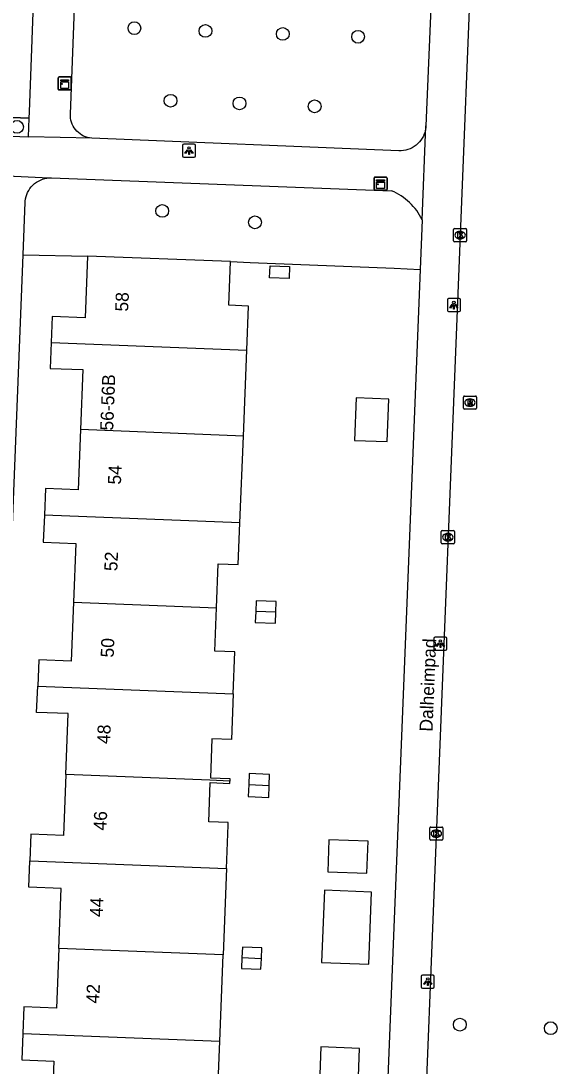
# Model space of a CAD drawing. Extents: x 160787 to 161428, y 386828 to 387483.
# Drawn here: x 161096.6 to 161137.7, y 387090.3 to 387170.3 of the extents above; entities that cross this region are included whole.
import ezdxf

# ---------------------------------------------------------------- set-up
doc = ezdxf.new("R2010")
doc.units = 0
for name, color, linetype in [('IMGEO_Boom', 7, 'Continuous'), ('IMGEO_Groenvoorziening', 7, 'Continuous'), ('IMGEO_Haag', 7, 'Continuous'), ('IMGEO_Hek', 7, 'Continuous'), ('IMGEO_Kast', 7, 'Continuous'), ('IMGEO_Kolk', 7, 'Continuous'), ('IMGEO_Lichtpunt', 7, 'Continuous'), ('IMGEO_Openbare_ruimte_label', 7, 'Continuous'), ('IMGEO_Pand', 7, 'Continuous'), ('IMGEO_Pand_nummerreeks', 7, 'Continuous'), ('IMGEO_Rioolput', 7, 'Continuous'), ('IMGEO_Voetpad_open', 7, 'Continuous')]:
    doc.layers.add(name, color=color, linetype=linetype)

msp = doc.modelspace()

# ---------------------------------------------------------------- linework, layer by layer
at = {"layer": 'IMGEO_Boom'}
for centre in [(161105.276, 387169.754), (161110.722, 387169.544), (161116.648, 387169.315), (161122.413, 387169.092), (161108.043, 387164.193), (161113.329, 387163.989), (161119.085, 387163.766), (161096.289, 387162.196), (161107.406, 387155.761), (161114.516, 387154.886), (161130.212, 387093.447), (161137.176, 387093.174)]:
    msp.add_circle(centre, 0.489, dxfattribs=at)
at = {"layer": 'IMGEO_Groenvoorziening'}
for points in [[(161095.222, 387162.927), (161097.214, 387162.854)], [(161096.743, 387152.402), (161101.691, 387152.304)], [(161112.644, 387151.876), (161114.144, 387151.817), (161125.178, 387151.362), (161127.175, 387151.273)]]:
    msp.add_lwpolyline(points, dxfattribs=at)
at = {"layer": 'IMGEO_Haag'}
msp.add_lwpolyline([(161097.214, 387162.854), (161095.222, 387162.927)], dxfattribs=at)
at = {"layer": 'IMGEO_Hek'}
msp.add_lwpolyline([(161097.214, 387162.854), (161087.423, 387163.212), (161083.345, 387163.361), (161081.407, 387163.432), (161075.331, 387163.654), (161075.116, 387163.662), (161074.598, 387163.681), (161071.304, 387163.802), (161070.928, 387163.815), (161063.158, 387164.099), (161059.142, 387164.246), (161052.353, 387164.535), (161051.029, 387164.592), (161046.982, 387164.764), (161046.647, 387164.778), (161038.81, 387165.111), (161034.783, 387165.283), (161026.6, 387165.631), (161022.975, 387165.785), (161022.636, 387165.799), (161014.462, 387166.146), (161011.004, 387166.293), (161000.917, 387166.722)], dxfattribs=at)
at = {"layer": 'IMGEO_Kast'}
for p, q in [((161099.438, 387165.094), (161099.438, 387165.935)), ((161099.438, 387165.935), (161099.438, 387165.094)), ((161099.513, 387166.019), (161100.354, 387166.019)), ((161100.354, 387166.019), (161099.513, 387166.019)), ((161100.438, 387165.944), (161100.438, 387165.103)), ((161100.438, 387165.103), (161100.438, 387165.944)), ((161100.363, 387165.019), (161099.522, 387165.019)), ((161099.522, 387165.019), (161100.363, 387165.019)), ((161123.637, 387157.414), (161123.637, 387158.255)), ((161123.637, 387158.255), (161123.637, 387157.414)), ((161123.712, 387158.339), (161124.553, 387158.339)), ((161124.553, 387158.339), (161123.712, 387158.339)), ((161124.637, 387158.264), (161124.637, 387157.423)), ((161124.637, 387157.423), (161124.637, 387158.264)), ((161124.562, 387157.339), (161123.721, 387157.339)), ((161123.721, 387157.339), (161124.562, 387157.339))]:
    msp.add_line(p, q, dxfattribs=at)
for points in [[(161099.633, 387165.809), (161100.233, 387165.809), (161100.233, 387165.724), (161099.633, 387165.724), (161099.633, 387165.809)], [(161099.633, 387165.634), (161100.233, 387165.634), (161100.233, 387165.145), (161099.633, 387165.145), (161099.633, 387165.634)], [(161123.832, 387158.129), (161124.432, 387158.129), (161124.432, 387158.044), (161123.832, 387158.044), (161123.832, 387158.129)], [(161123.832, 387157.954), (161124.432, 387157.954), (161124.432, 387157.465), (161123.832, 387157.465), (161123.832, 387157.954)]]:
    msp.add_lwpolyline(points, dxfattribs=at)
for centre in [(161099.717, 387165.483), (161123.916, 387157.803)]:
    msp.add_circle(centre, 0.0377, dxfattribs=at)
for centre, start, end in [((161099.516, 387165.941), 92.4484, 184.28452), ((161099.516, 387165.941), 92.4484, 184.28452), ((161100.36, 387165.941), 2.4484, 94.28452), ((161100.36, 387165.941), 2.4484, 94.28452), ((161099.516, 387165.097), 182.4484, 274.28452), ((161099.516, 387165.097), 182.4484, 274.28452), ((161100.36, 387165.097), 272.4484, 4.28452), ((161100.36, 387165.097), 272.4484, 4.28452), ((161123.715, 387158.261), 92.4484, 184.28452), ((161123.715, 387158.261), 92.4484, 184.28452), ((161124.559, 387158.261), 2.4484, 94.28452), ((161124.559, 387158.261), 2.4484, 94.28452), ((161123.715, 387157.417), 182.4484, 274.28452), ((161123.715, 387157.417), 182.4484, 274.28452), ((161124.559, 387157.417), 272.4484, 4.28452), ((161124.559, 387157.417), 272.4484, 4.28452)]:
    msp.add_arc(centre, 0.0779, start, end, dxfattribs=at)
at = {"layer": 'IMGEO_Kolk'}
for p, q in [((161129.733, 387153.477), (161129.733, 387154.329)), ((161129.808, 387154.403), (161130.66, 387154.403)), ((161130.221, 387154.183), (161130.246, 387154.183)), ((161130.734, 387154.329), (161130.734, 387153.477)), ((161130.66, 387153.403), (161129.808, 387153.403)), ((161130.244, 387153.623), (161130.219, 387153.623)), ((161128.867, 387131.275), (161129.719, 387131.275)), ((161128.792, 387130.349), (161128.792, 387131.201)), ((161129.303, 387130.495), (161129.278, 387130.495)), ((161129.28, 387131.055), (161129.305, 387131.055)), ((161129.793, 387131.201), (161129.793, 387130.349)), ((161129.719, 387130.275), (161128.867, 387130.275)), ((161127.906, 387107.655), (161127.906, 387108.507)), ((161127.981, 387108.581), (161128.833, 387108.581)), ((161128.394, 387108.361), (161128.419, 387108.361)), ((161128.907, 387108.507), (161128.907, 387107.655)), ((161128.833, 387107.581), (161127.981, 387107.581)), ((161128.417, 387107.801), (161128.392, 387107.801))]:
    msp.add_line(p, q, dxfattribs=at)
for points in [[(161129.733, 387153.477), (161129.733, 387154.329)], [(161129.808, 387154.403), (161130.66, 387154.403)], [(161130.054, 387154.103), (161130.177, 387154.103), (161130.177, 387153.952), (161130.307, 387154.103), (161130.471, 387154.103), (161130.325, 387153.952), (161130.478, 387153.703), (161130.326, 387153.703), (161130.241, 387153.867), (161130.177, 387153.8), (161130.177, 387153.703), (161130.054, 387153.703), (161130.054, 387154.103)], [(161130.734, 387154.329), (161130.734, 387153.477)], [(161130.66, 387153.403), (161129.808, 387153.403)], [(161128.867, 387131.275), (161129.719, 387131.275)], [(161128.792, 387130.349), (161128.792, 387131.201)], [(161129.113, 387130.975), (161129.236, 387130.975), (161129.236, 387130.824), (161129.366, 387130.975), (161129.53, 387130.975), (161129.384, 387130.824), (161129.537, 387130.575), (161129.385, 387130.575), (161129.3, 387130.739), (161129.236, 387130.672), (161129.236, 387130.575), (161129.113, 387130.575), (161129.113, 387130.975)], [(161129.793, 387131.201), (161129.793, 387130.349)], [(161129.719, 387130.275), (161128.867, 387130.275)], [(161127.906, 387107.655), (161127.906, 387108.507)], [(161127.981, 387108.581), (161128.833, 387108.581)], [(161128.227, 387108.281), (161128.35, 387108.281), (161128.35, 387108.13), (161128.48, 387108.281), (161128.644, 387108.281), (161128.498, 387108.13), (161128.651, 387107.881), (161128.499, 387107.881), (161128.414, 387108.045), (161128.35, 387107.978), (161128.35, 387107.881), (161128.227, 387107.881), (161128.227, 387108.281)], [(161128.907, 387108.507), (161128.907, 387107.655)], [(161128.833, 387107.581), (161127.981, 387107.581)]]:
    msp.add_lwpolyline(points, dxfattribs=at)
for centre, start, end in [((161129.81, 387154.327), 91.55205, 178.44795), ((161129.81, 387154.327), 91.55205, 178.44795), ((161130.658, 387154.327), 1.55205, 88.44795), ((161130.658, 387154.327), 1.55205, 88.44795), ((161129.81, 387153.479), 181.55205, 268.44795), ((161129.81, 387153.479), 181.55205, 268.44795), ((161130.658, 387153.479), 271.55205, 358.44795), ((161130.658, 387153.479), 271.55205, 358.44795), ((161128.869, 387131.199), 91.55205, 178.44795), ((161128.869, 387131.199), 91.55205, 178.44795), ((161129.717, 387131.199), 1.55205, 88.44795), ((161129.717, 387131.199), 1.55205, 88.44795), ((161128.869, 387130.351), 181.55205, 268.44795), ((161128.869, 387130.351), 181.55205, 268.44795), ((161129.717, 387130.351), 271.55205, 358.44795), ((161129.717, 387130.351), 271.55205, 358.44795), ((161127.983, 387108.505), 91.55205, 178.44795), ((161127.983, 387108.505), 91.55205, 178.44795), ((161128.831, 387108.505), 1.55205, 88.44795), ((161128.831, 387108.505), 1.55205, 88.44795), ((161127.983, 387107.657), 181.55205, 268.44795), ((161127.983, 387107.657), 181.55205, 268.44795), ((161128.831, 387107.657), 271.55205, 358.44795), ((161128.831, 387107.657), 271.55205, 358.44795)]:
    msp.add_arc(centre, 0.0765, start, end, dxfattribs=at)
for centre, major_axis, ratio, start_param, end_param in [((161130.22, 387153.903), (-0.387, 0.002), 0.722429, 4.712389, 7.853982), ((161130.245, 387153.903), (-0.39, 0.002), 0.717154, 1.570796, 4.712389), ((161129.279, 387130.775), (-0.387, 0.002), 0.722429, 4.712389, 7.853982), ((161129.304, 387130.775), (-0.39, 0.002), 0.717154, 1.570796, 4.712389), ((161128.393, 387108.081), (-0.387, 0.002), 0.722429, 4.712389, 7.853982), ((161128.418, 387108.081), (-0.39, 0.002), 0.717154, 1.570796, 4.712389)]:
    msp.add_ellipse(centre, major_axis=major_axis, ratio=ratio, start_param=start_param, end_param=end_param, dxfattribs=at)
at = {"layer": 'IMGEO_Lichtpunt'}
for p, q in [((161109.864, 387160.874), (161109.056, 387160.874)), ((161109.864, 387160.874), (161109.056, 387160.874)), ((161108.962, 387160.779), (161108.962, 387159.972)), ((161108.962, 387160.779), (161108.962, 387159.972)), ((161109.958, 387159.972), (161109.958, 387160.779)), ((161109.958, 387159.972), (161109.958, 387160.779)), ((161109.056, 387159.878), (161109.864, 387159.878)), ((161109.056, 387159.878), (161109.864, 387159.878)), ((161129.26, 387148.947), (161129.26, 387148.14)), ((161129.26, 387148.947), (161129.26, 387148.14)), ((161130.162, 387149.042), (161129.354, 387149.042)), ((161130.162, 387149.042), (161129.354, 387149.042)), ((161130.256, 387148.14), (161130.256, 387148.947)), ((161130.256, 387148.14), (161130.256, 387148.947)), ((161129.354, 387148.046), (161130.162, 387148.046)), ((161129.354, 387148.046), (161130.162, 387148.046)), ((161128.22, 387123.027), (161128.22, 387122.22)), ((161128.22, 387123.027), (161128.22, 387122.22)), ((161129.122, 387123.122), (161128.314, 387123.122)), ((161129.122, 387123.122), (161128.314, 387123.122)), ((161129.216, 387122.22), (161129.216, 387123.027)), ((161129.216, 387122.22), (161129.216, 387123.027)), ((161128.314, 387122.126), (161129.122, 387122.126)), ((161128.314, 387122.126), (161129.122, 387122.126)), ((161127.256, 387097.145), (161127.256, 387096.338)), ((161127.256, 387097.145), (161127.256, 387096.338)), ((161128.158, 387097.24), (161127.35, 387097.24)), ((161128.158, 387097.24), (161127.35, 387097.24)), ((161128.252, 387096.338), (161128.252, 387097.145)), ((161128.252, 387096.338), (161128.252, 387097.145)), ((161127.35, 387096.244), (161128.158, 387096.244)), ((161127.35, 387096.244), (161128.158, 387096.244))]:
    msp.add_line(p, q, dxfattribs=at)
for points in [[(161109.336, 387160.443), (161109.375, 387160.415), (161109.187, 387160.153), (161109.149, 387160.18), (161109.336, 387160.443)], [(161109.438, 387160.395), (161109.485, 387160.395), (161109.485, 387160.073), (161109.438, 387160.073), (161109.438, 387160.395)], [(161109.548, 387160.415), (161109.586, 387160.442), (161109.773, 387160.18), (161109.734, 387160.152), (161109.548, 387160.415)], [(161129.634, 387148.611), (161129.673, 387148.583), (161129.485, 387148.321), (161129.447, 387148.348), (161129.634, 387148.611)], [(161129.736, 387148.563), (161129.783, 387148.563), (161129.783, 387148.241), (161129.736, 387148.241), (161129.736, 387148.563)], [(161129.846, 387148.583), (161129.884, 387148.61), (161130.071, 387148.348), (161130.032, 387148.32), (161129.846, 387148.583)], [(161128.594, 387122.691), (161128.633, 387122.663), (161128.445, 387122.401), (161128.407, 387122.428), (161128.594, 387122.691)], [(161128.696, 387122.643), (161128.743, 387122.643), (161128.743, 387122.321), (161128.696, 387122.321), (161128.696, 387122.643)], [(161128.806, 387122.663), (161128.844, 387122.69), (161129.031, 387122.428), (161128.992, 387122.4), (161128.806, 387122.663)], [(161127.63, 387096.809), (161127.669, 387096.781), (161127.481, 387096.519), (161127.443, 387096.546), (161127.63, 387096.809)], [(161127.732, 387096.761), (161127.779, 387096.761), (161127.779, 387096.439), (161127.732, 387096.439), (161127.732, 387096.761)], [(161127.842, 387096.781), (161127.88, 387096.808), (161128.067, 387096.546), (161128.028, 387096.518), (161127.842, 387096.781)]]:
    msp.add_lwpolyline(points, dxfattribs=at)
for centre in [(161109.461, 387160.577), (161129.759, 387148.745), (161128.719, 387122.825), (161127.755, 387096.943)]:
    msp.add_circle(centre, 0.0994, dxfattribs=at)
for centre, start, end in [((161109.056, 387160.779), 90, 180), ((161109.056, 387160.779), 90, 180), ((161109.864, 387160.779), 0, 90), ((161109.864, 387160.779), 0, 90), ((161109.056, 387159.972), 180, 270), ((161109.056, 387159.972), 180, 270), ((161109.864, 387159.972), 270, 0), ((161109.864, 387159.972), 270, 360), ((161129.354, 387148.947), 90, 180), ((161129.354, 387148.947), 90, 180), ((161130.162, 387148.947), 0, 90), ((161130.162, 387148.947), 0, 90), ((161129.354, 387148.14), 180, 270), ((161129.354, 387148.14), 180, 270), ((161130.162, 387148.14), 270, 0), ((161130.162, 387148.14), 270, 360), ((161128.314, 387123.027), 90, 180), ((161128.314, 387123.027), 90, 180), ((161129.122, 387123.027), 0, 90), ((161129.122, 387123.027), 0, 90), ((161128.314, 387122.22), 180, 270), ((161128.314, 387122.22), 180, 270), ((161129.122, 387122.22), 270, 0), ((161129.122, 387122.22), 270, 360), ((161127.35, 387097.145), 90, 180), ((161127.35, 387097.145), 90, 180), ((161128.158, 387097.145), 0, 90), ((161128.158, 387097.145), 0, 90), ((161127.35, 387096.338), 180, 270), ((161127.35, 387096.338), 180, 270), ((161128.158, 387096.338), 270, 0), ((161128.158, 387096.338), 270, 360)]:
    msp.add_arc(centre, 0.0946, start, end, dxfattribs=at)
at = {"layer": 'IMGEO_Pand'}
for points in [[(161101.691, 387152.304), (161101.506, 387147.562), (161098.987, 387147.661), (161098.909, 387145.68)], [(161112.644, 387151.876), (161101.691, 387152.304)], [(161113.881, 387145.095), (161114.013, 387148.471), (161112.513, 387148.53), (161112.644, 387151.876)], [(161115.672, 387151.557), (161117.16, 387151.498), (161117.124, 387150.578), (161115.636, 387150.637), (161115.672, 387151.557)], [(161098.909, 387145.68), (161098.832, 387143.701), (161101.33, 387143.603), (161101.151, 387139.008)], [(161098.909, 387145.68), (161113.881, 387145.095)], [(161113.624, 387138.52), (161113.881, 387145.095)], [(161124.775, 387141.336), (161122.277, 387141.434), (161122.147, 387138.187), (161124.645, 387138.089), (161124.775, 387141.336)], [(161101.151, 387139.008), (161100.971, 387134.408), (161098.457, 387134.506), (161098.376, 387132.45)], [(161113.624, 387138.52), (161101.151, 387139.008)], [(161113.364, 387131.864), (161113.624, 387138.52)], [(161098.376, 387132.45), (161098.296, 387130.396), (161100.781, 387130.299), (161100.605, 387125.795)], [(161113.364, 387131.864), (161098.376, 387132.45)], [(161111.571, 387125.366), (161111.703, 387128.73), (161113.239, 387128.67), (161113.364, 387131.864)], [(161100.605, 387125.795), (161100.429, 387121.288), (161097.943, 387121.386), (161097.864, 387119.372)], [(161100.605, 387125.795), (161111.571, 387125.366)], [(161116.113, 387125.025), (161116.144, 387125.838), (161114.607, 387125.898), (161114.575, 387125.085)], [(161112.853, 387118.786), (161112.978, 387121.99), (161111.442, 387122.05), (161111.571, 387125.366)], [(161114.575, 387125.085), (161114.542, 387124.248), (161116.08, 387124.188), (161116.113, 387125.025)], [(161116.113, 387125.025), (161114.575, 387125.085)], [(161100.026, 387112.595), (161100.208, 387117.265), (161097.786, 387117.36), (161097.864, 387119.372)], [(161097.864, 387119.372), (161112.853, 387118.786)], [(161112.853, 387118.786), (161112.716, 387115.282), (161111.216, 387115.34), (161111.099, 387112.342), (161112.598, 387112.284), (161112.591, 387112.104)], [(161100.026, 387112.595), (161099.843, 387107.923), (161097.349, 387108.021), (161097.27, 387105.995)], [(161112.591, 387112.104), (161111.055, 387112.164), (161100.026, 387112.595)], [(161112.33, 387105.406), (161112.46, 387108.732), (161112.467, 387108.926), (161110.968, 387108.985), (161111.085, 387111.983), (161112.584, 387111.924), (161112.591, 387112.104)], [(161115.605, 387111.767), (161115.638, 387112.61), (161114.069, 387112.672), (161114.036, 387111.828)], [(161114.036, 387111.828), (161114, 387110.913), (161115.569, 387110.851), (161115.605, 387111.767)], [(161114.036, 387111.828), (161115.605, 387111.767)], [(161120.09, 387105.159), (161123.097, 387105.058), (161123.18, 387107.501), (161120.172, 387107.602), (161120.09, 387105.159)], [(161099.476, 387099.29), (161099.656, 387103.875), (161097.191, 387103.971), (161097.27, 387105.995)], [(161097.27, 387105.995), (161112.33, 387105.406)], [(161112.33, 387105.406), (161112.071, 387098.797)], [(161119.618, 387098.218), (161123.227, 387098.077), (161123.443, 387103.596), (161119.834, 387103.737), (161119.618, 387098.218)], [(161099.476, 387099.29), (161099.297, 387094.705), (161096.813, 387094.802), (161096.734, 387092.778)], [(161112.071, 387098.797), (161099.476, 387099.29)], [(161115.006, 387098.517), (161115.038, 387099.326), (161113.546, 387099.385), (161113.514, 387098.576)], [(161111.813, 387092.188), (161112.071, 387098.797)], [(161113.514, 387098.576), (161113.482, 387097.756), (161114.974, 387097.697), (161115.006, 387098.517)], [(161113.514, 387098.576), (161115.006, 387098.517)], [(161096.734, 387092.778), (161096.655, 387090.756), (161099.09, 387090.661), (161098.911, 387086.078)], [(161096.734, 387092.778), (161111.813, 387092.188)], [(161109.909, 387085.648), (161110.043, 387089.094), (161111.69, 387089.03), (161111.813, 387092.188)], [(161119.489, 387089.621), (161122.448, 387089.506), (161122.531, 387091.622), (161119.572, 387091.737), (161119.489, 387089.621)]]:
    msp.add_lwpolyline(points, dxfattribs=at)
at = {"layer": 'IMGEO_Rioolput'}
for p, q in [((161130.484, 387140.657), (161130.484, 387141.509)), ((161130.559, 387141.583), (161131.411, 387141.583)), ((161130.972, 387141.363), (161130.997, 387141.363)), ((161131.485, 387141.509), (161131.485, 387140.657)), ((161131.411, 387140.583), (161130.559, 387140.583)), ((161130.995, 387140.803), (161130.97, 387140.803))]:
    msp.add_line(p, q, dxfattribs=at)
for points in [[(161130.484, 387140.657), (161130.484, 387141.509)], [(161130.559, 387141.583), (161131.411, 387141.583)], [(161131.073, 387141.281), (161130.821, 387141.283), (161130.821, 387140.883)], [(161130.821, 387140.883), (161130.945, 387140.883), (161130.945, 387141.045), (161130.956, 387141.045)], [(161130.999, 387141.202), (161130.945, 387141.202), (161130.945, 387141.121)], [(161130.945, 387141.121), (161130.997, 387141.121)], [(161131.003, 387141.016), (161131.074, 387140.883), (161131.214, 387140.883), (161131.149, 387141.009)], [(161131.485, 387141.509), (161131.485, 387140.657)], [(161131.411, 387140.583), (161130.559, 387140.583)]]:
    msp.add_lwpolyline(points, dxfattribs=at)
for centre, radius, start, end in [((161130.561, 387141.507), 0.0765, 91.55205, 178.44795), ((161130.561, 387141.507), 0.0765, 91.55205, 178.44795), ((161130.955, 387140.992), 0.0533, 26.02933, 88.69889), ((161130.981, 387141.31), 0.19, 274.7715, 282.96867), ((161131.005, 387141.106), 0.0964, 77.00612, 93.18647), ((161131.019, 387141.163), 0.0378, 276.66336, 79.67722), ((161131.072, 387141.171), 0.109, 350.36119, 89.41601), ((161131.07, 387141.171), 0.112, 277.58423, 350.98172), ((161131.054, 387140.956), 0.108, 29.51342, 73.79051), ((161131.409, 387141.507), 0.0765, 1.55205, 88.44795), ((161131.409, 387141.507), 0.0765, 1.55205, 88.44795), ((161130.561, 387140.659), 0.0765, 181.55205, 268.44795), ((161130.561, 387140.659), 0.0765, 181.55205, 268.44795), ((161131.409, 387140.659), 0.0765, 271.55205, 358.44795), ((161131.409, 387140.659), 0.0765, 271.55205, 358.44795)]:
    msp.add_arc(centre, radius, start, end, dxfattribs=at)
for centre, major_axis, ratio, start_param, end_param in [((161130.971, 387141.083), (-0.387, 0.002), 0.722429, 4.712389, 7.853982), ((161130.996, 387141.083), (-0.39, 0.002), 0.717154, 1.570796, 4.712389)]:
    msp.add_ellipse(centre, major_axis=major_axis, ratio=ratio, start_param=start_param, end_param=end_param, dxfattribs=at)
at = {"layer": 'IMGEO_Voetpad_open'}
for points in [[(161129.056, 387074.52), (161128.963, 387074.526), (161128.79, 387074.549), (161128.619, 387074.587), (161128.453, 387074.64), (161128.292, 387074.708), (161128.138, 387074.79), (161127.991, 387074.886), (161127.854, 387074.994), (161127.727, 387075.114), (161127.611, 387075.245), (161127.508, 387075.386), (161127.417, 387075.535), (161127.34, 387075.692), (161127.278, 387075.856), (161127.23, 387076.024), (161127.198, 387076.195), (161127.18, 387076.369), (161127.179, 387076.544), (161131.384, 387182.078), (161131.407, 387182.665)], [(161097.214, 387162.854), (161097.233, 387163.345), (161097.659, 387174.419)], [(161102.003, 387161.321), (161101.844, 387161.343), (161101.688, 387161.378), (161101.535, 387161.427), (161101.387, 387161.49), (161101.245, 387161.566), (161101.111, 387161.654), (161100.985, 387161.753), (161100.869, 387161.864), (161100.763, 387161.984), (161100.668, 387162.114), (161100.585, 387162.251), (161100.514, 387162.395), (161100.457, 387162.545), (161100.413, 387162.7), (161100.384, 387162.858), (161100.368, 387163.017), (161100.367, 387163.178), (161100.785, 387174.019)], [(161128.061, 387173.149), (161127.614, 387162.268)], [(161097.16, 387161.441), (161097.214, 387162.854)], [(161087.364, 387161.825), (161097.16, 387161.441)], [(161127.614, 387162.268), (161127.608, 387162.174), (161127.584, 387161.997), (161127.544, 387161.822), (161127.488, 387161.652), (161127.418, 387161.488), (161127.333, 387161.33), (161127.235, 387161.181), (161127.123, 387161.041), (161127, 387160.911), (161126.865, 387160.793), (161126.721, 387160.688), (161126.568, 387160.596), (161126.407, 387160.518), (161126.239, 387160.454), (161126.067, 387160.406), (161125.891, 387160.373), (161125.713, 387160.357), (161125.534, 387160.356), (161102.003, 387161.321)], [(161127.328, 387155.07), (161127.614, 387162.268)], [(161102.003, 387161.321), (161097.16, 387161.441)], [(161090.7, 387158.68), (161098.746, 387158.282)], [(161096.743, 387152.402), (161096.903, 387156.419), (161096.909, 387156.512), (161096.932, 387156.684), (161096.97, 387156.854), (161097.024, 387157.019), (161097.092, 387157.179), (161097.174, 387157.333), (161097.269, 387157.478), (161097.377, 387157.614), (161097.497, 387157.74), (161097.627, 387157.855), (161097.767, 387157.958), (161097.916, 387158.048), (161098.072, 387158.124), (161098.235, 387158.186), (161098.402, 387158.233), (161098.573, 387158.265), (161098.746, 387158.282)], [(161098.746, 387158.282), (161098.92, 387158.283), (161124.982, 387157.29)], [(161127.328, 387155.07), (161127.175, 387151.273)], [(161094.57, 387048.71), (161094.477, 387048.716), (161094.304, 387048.739), (161094.133, 387048.777), (161093.967, 387048.83), (161093.806, 387048.898), (161093.652, 387048.98), (161093.505, 387049.076), (161093.368, 387049.184), (161093.241, 387049.304), (161093.125, 387049.435), (161093.022, 387049.576), (161092.931, 387049.725), (161092.854, 387049.882), (161092.792, 387050.046), (161092.744, 387050.214), (161092.712, 387050.385), (161092.694, 387050.559), (161092.693, 387050.734), (161094.68, 387100.61), (161096.743, 387152.402)], [(161127.175, 387151.273), (161124.099, 387074.719)]]:
    msp.add_lwpolyline(points, dxfattribs=at)
msp.add_arc((161123.303, 387153.167), 4.452, 25.31168, 67.8497, dxfattribs=at)

# ---------------------------------------------------------------- texts
at = {"layer": 'IMGEO_Openbare_ruimte_label'}
msp.add_text('Dalheimpad', height=1, rotation=87.64984, dxfattribs=at).set_placement((161128.114, 387115.869))
at = {"layer": 'IMGEO_Pand_nummerreeks'}
for s, rotation, p in [('58', 87.59952, (161104.795, 387148.033)), ('56-56B', 87.7714, (161103.649, 387138.923)), ('54', 87.60171, (161104.24, 387134.786)), ('52', 87.59952, (161103.963, 387128.16)), ('50', 87.59952, (161103.685, 387121.543)), ('48', 87.59952, (161103.408, 387114.921)), ('46', 87.59952, (161103.131, 387108.296)), ('44', 87.60171, (161102.853, 387101.675)), ('42', 87.60171, (161102.576, 387095.049))]:
    msp.add_text(s, height=1, rotation=rotation, dxfattribs=at).set_placement(p)

doc.saveas('drawing.dxf')
